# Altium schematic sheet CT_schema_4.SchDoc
size 287 x 169 mm
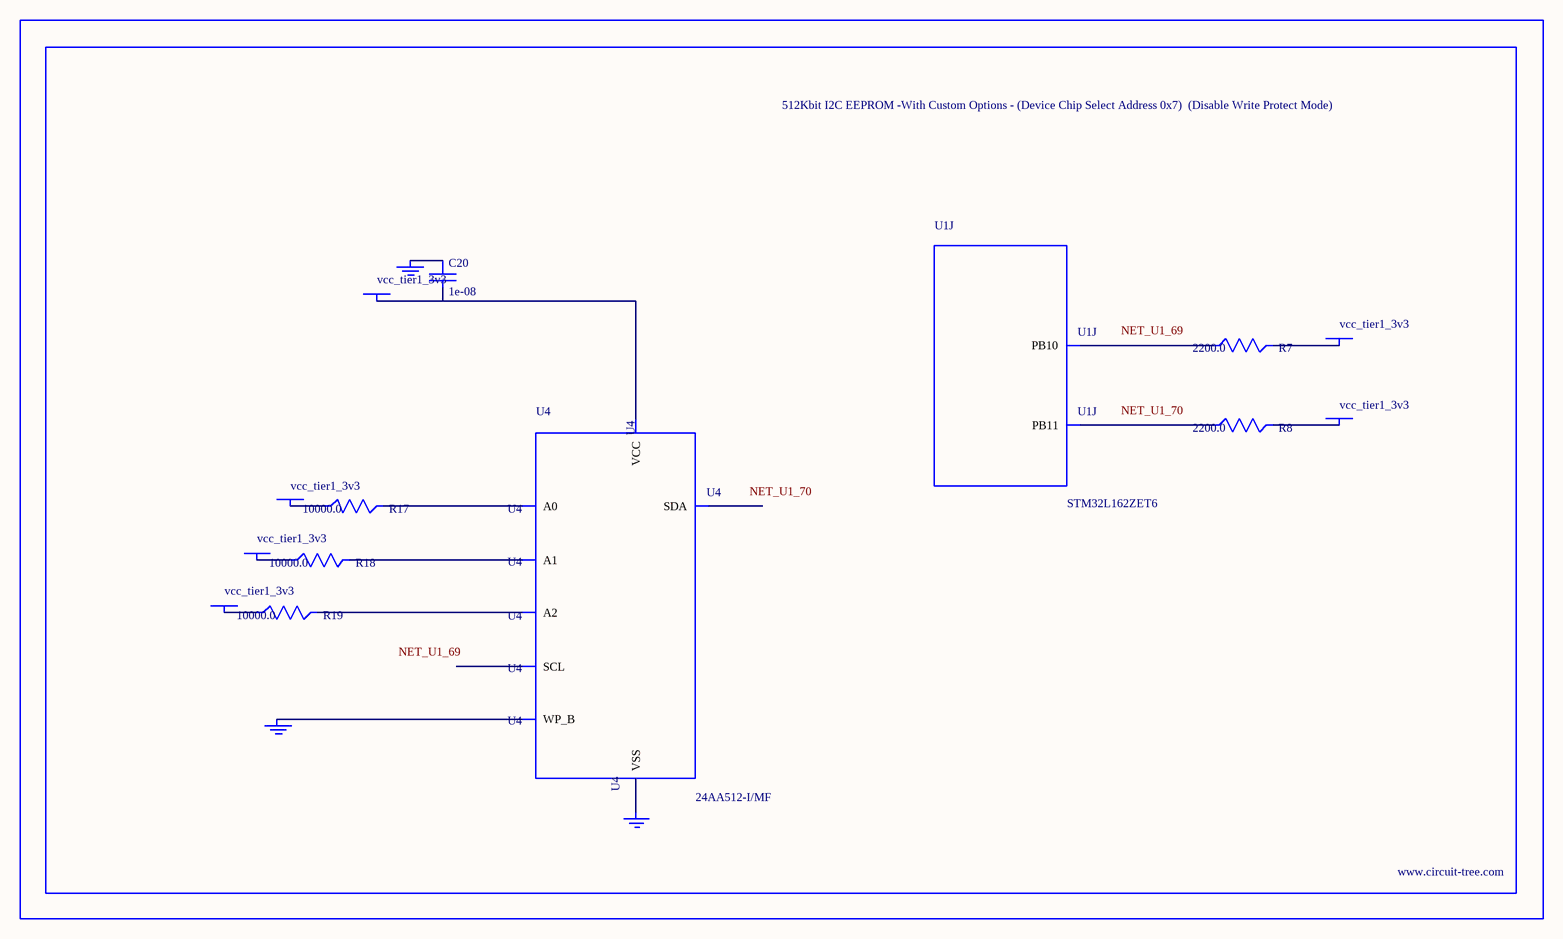
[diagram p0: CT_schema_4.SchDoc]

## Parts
BORDER3  (no value)
C20  1e-08  [C0402]
GND_INSTANCE_3_0  (no value)
GND_INSTANCE_3_1  (no value)
GND_INSTANCE_3_2  (no value)
POWER_INSTANCE_3_0  vcc_tier1_3v3
POWER_INSTANCE_3_1  vcc_tier1_3v3
POWER_INSTANCE_3_2  vcc_tier1_3v3
POWER_INSTANCE_3_3  vcc_tier1_3v3
POWER_INSTANCE_3_4  vcc_tier1_3v3
POWER_INSTANCE_3_5  vcc_tier1_3v3
R7  2200.0  [R0603]
R8  2200.0  [R0603]
R17  10000.0  [R0603]
R18  10000.0  [R0603]
R19  10000.0  [R0603]
U1  STM32L162ZET6  [LQFP144]  (part J of 13)
U4  24AA512-I/MF  [DFN8-S]

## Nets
NetC20_1: C20.1 GND_INSTANCE_3_1.0(GND)
NetC20_2: C20.2 POWER_INSTANCE_3_3.0(PWR) U4.8(VCC)
NetGND_INSTANCE_3_0_0: GND_INSTANCE_3_0.0(GND) U4.7(WP_B)
NetGND_INSTANCE_3_2_0: GND_INSTANCE_3_2.0(GND) U4.4(VSS)
NetPOWER_INSTANCE_3_0_0: POWER_INSTANCE_3_0.0(PWR) R17.1
NetPOWER_INSTANCE_3_1_0: POWER_INSTANCE_3_1.0(PWR) R18.1
NetPOWER_INSTANCE_3_2_0: POWER_INSTANCE_3_2.0(PWR) R19.1
NetPOWER_INSTANCE_3_4_0: POWER_INSTANCE_3_4.0(PWR) R7.2
NetPOWER_INSTANCE_3_5_0: POWER_INSTANCE_3_5.0(PWR) R8.2
NetR7_1: R7.1 U1.69(PB10)
NetR8_1: R8.1 U1.70(PB11)
NetR17_2: R17.2 U4.1(A0)
NetR18_2: R18.2 U4.2(A1)
NetR19_2: R19.2 U4.3(A2)

Not connected (* = marked no-connect by the designer): U4 5(SDA) 6(SCL)

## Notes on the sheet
- Labels drawn without touching a wire or pin: NET_U1_69, NET_U1_70

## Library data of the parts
BORDER3 = BORDER_PAGE3
C20 = C0402C103K3RAC
GND_INSTANCE_3_0-GND_INSTANCE_3_2 = GND
POWER_INSTANCE_3_0-POWER_INSTANCE_3_5 = PWR
R7 R8 = RC0603JR-072K2L
R17-R19 = RC0603JR-0710KL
